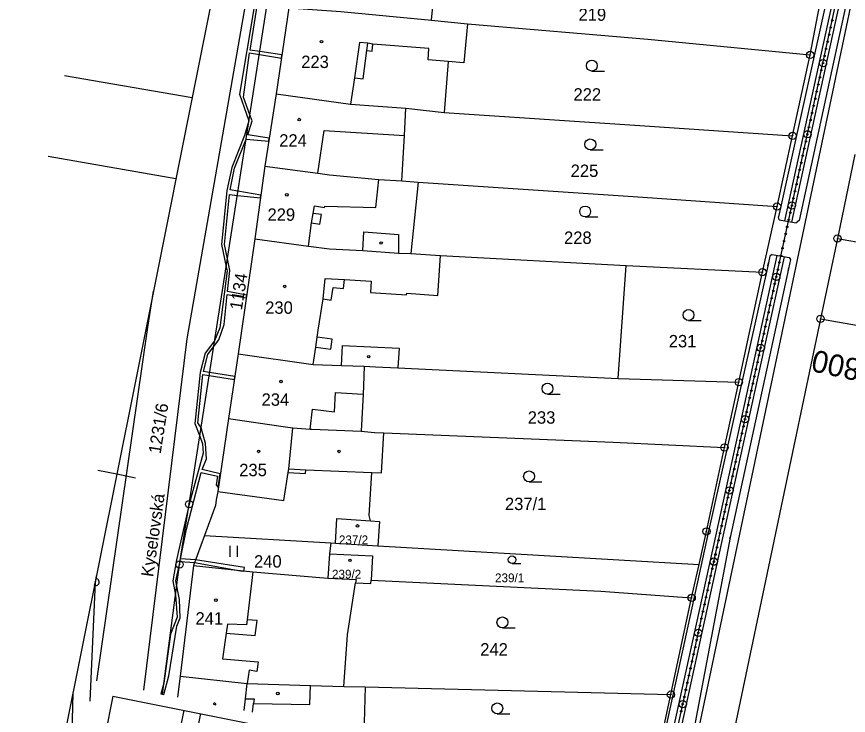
# Model space of a CAD drawing. Extents: x -548552 to -543113, y -1131925 to -1123599.
# Drawn here: x -547742 to -547627.8, y -1128838.5 to -1128742.6 of the extents above; entities that cross this region are included whole.
import ezdxf

# ---------------------------------------------------------------- set-up
doc = ezdxf.new("R2010")
doc.units = 0
for name, color, linetype in [('Hranice parcel', 7, 'Continuous'), ('HRANY', 7, 'Continuous'), ('Parcelní čísla', 7, 'Continuous'), ('Pop  PČ popisy', 7, 'Continuous'), ('Profile', 7, 'Continuous'), ('PROFILY NÁVRH', 7, 'Continuous'), ('STANIČENÍ', 7, 'Continuous'), ('Vnitřní kresba', 7, 'Continuous'), ('Vrstva 8', 7, 'Continuous'), ('Věcná břemena k části', 7, 'Continuous'), ('Značky bodu BP', 7, 'Continuous'), ('Značky budov', 7, 'Continuous'), ('Značky kultur', 7, 'Continuous')]:
    doc.layers.add(name, color=color, linetype=linetype)

msp = doc.modelspace()

# ---------------------------------------------------------------- linework, layer by layer
at = {"layer": 'Hranice parcel'}
for p, q in [((-547633.04, -1128747.88), (-547631.47, -1128739.69)), ((-547704.58, -1128741.4), (-547706.36, -1128753.23)), ((-547685.02, -1128743.12), (-547680.09, -1128743.61)), ((-547635.45, -1128758.96), (-547633.04, -1128747.88)), ((-547735.4, -1128750.68), (-547717.86, -1128753.7)), ((-547706.36, -1128753.23), (-547707.88, -1128763.12)), ((-547688.53, -1128755.18), (-547683.26, -1128755.76)), ((-547637.59, -1128768.68), (-547635.45, -1128758.96)), ((-547737.62, -1128761.78), (-547720.09, -1128764.83)), ((-547626.9, -1128761.54), (-547629.31, -1128773.05)), ((-547707.88, -1128763.12), (-547709.27, -1128773.09)), ((-547689.07, -1128765.13), (-547686.87, -1128765.32)), ((-547686.87, -1128765.32), (-547687.85, -1128775.09)), ((-547639.6, -1128777.67), (-547637.59, -1128768.68)), ((-547709.27, -1128773.09), (-547711.54, -1128788.87)), ((-547629.31, -1128773.05), (-547631.63, -1128784.07)), ((-547629.31, -1128773.05), (-547600.12, -1128778.08)), ((-547659.38, -1128792.25), (-547658.28, -1128776.77)), ((-547658.28, -1128776.77), (-547639.6, -1128777.67)), ((-547642.84, -1128792.75), (-547639.6, -1128777.67)), ((-547631.63, -1128784.07), (-547657.34, -1128906.42)), ((-547631.63, -1128784.07), (-547602.34, -1128789.17)), ((-547711.54, -1128788.87), (-547712.89, -1128797.72)), ((-547659.38, -1128792.25), (-547642.84, -1128792.75)), ((-547644.81, -1128801.71), (-547642.84, -1128792.75)), ((-547716.19, -1128813.8), (-547717.69, -1128817.92)), ((-547716.19, -1128813.8), (-547698.83, -1128814.81)), ((-547698.83, -1128814.81), (-547699.04, -1128816.28)), ((-547698.83, -1128814.81), (-547698.21, -1128814.85)), ((-547698.21, -1128814.85), (-547692.37, -1128815.19)), ((-547692.37, -1128815.19), (-547648.29, -1128817.77)), ((-547699.04, -1128816.28), (-547699.24, -1128819.63)), ((-547717.69, -1128817.92), (-547719.5, -1128833.1)), ((-547649.31, -1128822.34), (-547648.29, -1128817.77)), ((-547652.15, -1128835.61), (-547649.31, -1128822.34)), ((-547719.5, -1128833.1), (-547719.9, -1128835.94)), ((-547697.04, -1128834.48), (-547694.14, -1128834.56)), ((-547694.14, -1128834.56), (-547694.36, -1128844.22)), ((-547694.14, -1128834.56), (-547652.15, -1128835.61)), ((-547654.13, -1128844.61), (-547652.15, -1128835.61))]:
    msp.add_line(p, q, dxfattribs=at)
for points in [[(-547661.19, -1128917.7), (-547662.18, -1128906.21), (-547607.96, -1128648.53), (-547605.32, -1128634.46), (-547602.31, -1128618.85), (-547594.66, -1128568.22), (-547592.34, -1128552.17)], [(-547721.95, -1128835.53), (-547719.59, -1128817.77), (-547718.29, -1128809.48), (-547704.49, -1128721.23), (-547694.62, -1128699.9), (-547694.57, -1128699.7)], [(-547685.02, -1128743.12), (-547684.58, -1128738.45), (-547684.26, -1128735.01)], [(-547704.58, -1128741.4), (-547697.48, -1128741.93), (-547685.02, -1128743.12)], [(-547680.09, -1128743.61), (-547680.59, -1128748.96), (-547682.74, -1128748.77), (-547683.26, -1128755.76)], [(-547680.09, -1128743.61), (-547655.34, -1128745.73), (-547633.04, -1128747.88)], [(-547706.36, -1128753.23), (-547696.13, -1128754.63), (-547688.53, -1128755.18)], [(-547689.07, -1128765.13), (-547688.71, -1128758.94), (-547688.53, -1128755.18)], [(-547683.26, -1128755.76), (-547656.41, -1128757.55), (-547635.45, -1128758.96)], [(-547707.88, -1128763.12), (-547700.6, -1128764.09), (-547699.04, -1128764.34), (-547692.24, -1128764.94), (-547689.07, -1128765.13)], [(-547686.87, -1128765.32), (-547657.36, -1128767.28), (-547637.59, -1128768.68)], [(-547709.27, -1128773.09), (-547701.9, -1128774.08), (-547699.03, -1128774.45), (-547694.46, -1128774.7), (-547689.57, -1128775.05), (-547687.85, -1128775.09)], [(-547687.85, -1128775.09), (-547683.77, -1128775.4), (-547658.28, -1128776.77)], [(-547711.54, -1128788.87), (-547701.24, -1128790.31), (-547697.36, -1128790.46), (-547694.27, -1128790.57)], [(-547694.27, -1128790.57), (-547694.36, -1128793.25), (-547694.42, -1128794.38), (-547694.67, -1128799.49)], [(-547694.27, -1128790.57), (-547692.72, -1128790.65), (-547689.62, -1128790.8), (-547659.38, -1128792.25)], [(-547712.89, -1128797.72), (-547714.36, -1128807.74), (-547714.56, -1128808.88), (-547714.68, -1128809.68), (-547716.19, -1128813.8)], [(-547712.89, -1128797.72), (-547705.05, -1128798.86), (-547704.07, -1128799.01), (-547701.69, -1128799.19), (-547701.46, -1128799.21), (-547694.67, -1128799.49)], [(-547694.67, -1128799.49), (-547692.83, -1128799.64), (-547691.56, -1128799.69)], [(-547693.37, -1128811.78), (-547693.58, -1128811.04), (-547693.2, -1128805.15), (-547691.88, -1128805.2), (-547691.56, -1128799.69)], [(-547691.56, -1128799.69), (-547660.09, -1128800.98), (-547644.81, -1128801.71)], [(-547648.29, -1128817.77), (-547647.28, -1128813.22), (-547644.81, -1128801.71)], [(-547698.21, -1128814.85), (-547698.01, -1128811.44), (-547693.37, -1128811.78)], [(-547693.37, -1128811.78), (-547692.17, -1128811.88), (-547692.37, -1128815.19)], [(-547699.04, -1128816.28), (-547693.12, -1128816.58), (-547693.32, -1128819.91)], [(-547717.69, -1128817.92), (-547709.55, -1128818.79), (-547699.24, -1128819.63)], [(-547731.26, -1128820.58), (-547731.14, -1128820.17), (-547731.01, -1128819.32)], [(-547699.24, -1128819.63), (-547695.38, -1128819.81), (-547695.45, -1128820.26)], [(-547697.04, -1128834.48), (-547696.56, -1128827.4), (-547695.45, -1128820.26)], [(-547695.45, -1128820.26), (-547693.35, -1128820.39), (-547693.32, -1128819.91)], [(-547693.32, -1128819.91), (-547661.76, -1128821.44), (-547649.31, -1128822.34)], [(-547719.5, -1128833.1), (-547710.31, -1128834.1), (-547701.61, -1128834.34), (-547697.04, -1128834.48)], [(-547734.23, -1128835.38), (-547734.5, -1128844.62), (-547735.13, -1128852.83)]]:
    msp.add_lwpolyline(points, dxfattribs=at)
at = {"layer": 'HRANY'}
for p, q in [((-547637.29, -1128770.51), (-547634.95, -1128770.92)), ((-547638.26, -1128775.26), (-547635.92, -1128775.66))]:
    msp.add_line(p, q, dxfattribs=at)
at = {"layer": 'Profile'}
for p, q in [((-547702.64, -1128677.78), (-547725.75, -1128793.06)), ((-547702.64, -1128677.78), (-547725.75, -1128793.06)), ((-547702.64, -1128677.78), (-547725.75, -1128793.06)), ((-547725.75, -1128793.06), (-547748.86, -1128908.34)), ((-547725.75, -1128793.06), (-547748.86, -1128908.34)), ((-547725.75, -1128793.06), (-547748.86, -1128908.34)), ((-547725.75, -1128793.06), (-547743.85, -1128883.36)), ((-547728.22, -1128805.39), (-547730.81, -1128804.87)), ((-547725.63, -1128805.91), (-547728.22, -1128805.39))]:
    msp.add_line(p, q, dxfattribs=at)
at = {"layer": 'PROFILY NÁVRH'}
for p, q in [((-547631, -1128741.19), (-547637.38, -1128770.08)), ((-547636.53, -1128770.64), (-547629.99, -1128740.72)), ((-547635.54, -1128770.81), (-547629.01, -1128740.93)), ((-547628.2, -1128741.26), (-547634.57, -1128770.56)), ((-547637.29, -1128770.51), (-547637.38, -1128770.08)), ((-547634.57, -1128770.56), (-547634.95, -1128770.92)), ((-547645.92, -1128813.48), (-547637.56, -1128775.38)), ((-547644.94, -1128813.69), (-547636.58, -1128775.55)), ((-547638.58, -1128775.48), (-547638.83, -1128776.62)), ((-547638.26, -1128775.26), (-547638.58, -1128775.48)), ((-547635.73, -1128775.91), (-547636.02, -1128777.23)), ((-547635.92, -1128775.66), (-547635.73, -1128775.91)), ((-547638.83, -1128776.62), (-547647.04, -1128813.42)), ((-547636.02, -1128777.23), (-547644.03, -1128814.07)), ((-547647.04, -1128813.42), (-547654.58, -1128847.9)), ((-547653.49, -1128848.05), (-547645.92, -1128813.48)), ((-547652.51, -1128848.26), (-547644.94, -1128813.69)), ((-547644.03, -1128814.07), (-547650.58, -1128848.76))]:
    msp.add_line(p, q, dxfattribs=at)
at = {"layer": 'STANIČENÍ'}
for p, q in [((-547637.12, -1128775.69), (-547629.5, -1128740.83)), ((-547645.43, -1128813.59), (-547637.12, -1128775.69)), ((-547638.87, -1128776.8), (-547638.78, -1128776.4)), ((-547636.08, -1128777.54), (-547635.98, -1128777.08)), ((-547653, -1128848.16), (-547645.43, -1128813.59)), ((-547647.09, -1128813.62), (-547647, -1128813.24)), ((-547644.07, -1128814.26), (-547643.99, -1128813.9))]:
    msp.add_line(p, q, dxfattribs=at)
for centre, radius in [((-547630.22, -1128744.11), 0.1), ((-547630, -1128743.13), 0.1), ((-547630.43, -1128745.08), 0.1), ((-547630.64, -1128746.06), 0.1), ((-547630.86, -1128747.04), 0.1), ((-547631.28, -1128748.99), 0.5), ((-547631.07, -1128748.01), 0.1), ((-547631.28, -1128748.99), 0.1), ((-547631.71, -1128750.94), 0.1), ((-547631.5, -1128749.97), 0.1), ((-547631.92, -1128751.92), 0.1), ((-547632.14, -1128752.9), 0.1), ((-547632.35, -1128753.87), 0.1), ((-547632.57, -1128754.85), 0.1), ((-547632.78, -1128755.83), 0.1), ((-547633.21, -1128757.78), 0.1), ((-547632.99, -1128756.8), 0.1), ((-547633.42, -1128758.76), 0.5), ((-547633.42, -1128758.76), 0.1), ((-547633.63, -1128759.74), 0.1), ((-547633.85, -1128760.71), 0.1), ((-547634.06, -1128761.69), 0.1), ((-547634.27, -1128762.67), 0.1), ((-547634.7, -1128764.62), 0.1), ((-547634.49, -1128763.64), 0.1), ((-547634.91, -1128765.6), 0.1), ((-547635.13, -1128766.57), 0.1), ((-547635.34, -1128767.55), 0.1), ((-547635.55, -1128768.53), 0.5), ((-547635.55, -1128768.53), 0.1), ((-547635.77, -1128769.5), 0.1), ((-547636.2, -1128771.46), 0.1), ((-547635.98, -1128770.48), 0.1), ((-547636.41, -1128772.43), 0.1), ((-547636.62, -1128773.41), 0.1), ((-547636.84, -1128774.39), 0.1), ((-547637.05, -1128775.37), 0.1), ((-547637.26, -1128776.34), 0.1), ((-547637.69, -1128778.3), 0.5), ((-547637.69, -1128778.3), 0.1), ((-547637.48, -1128777.32), 0.1), ((-547637.91, -1128779.27), 0.1), ((-547638.12, -1128780.25), 0.1), ((-547638.33, -1128781.23), 0.1), ((-547638.55, -1128782.2), 0.1), ((-547638.76, -1128783.18), 0.1), ((-547639.19, -1128785.13), 0.1), ((-547638.98, -1128784.16), 0.1), ((-547639.4, -1128786.11), 0.1), ((-547639.62, -1128787.09), 0.1), ((-547639.83, -1128788.06), 0.5), ((-547639.83, -1128788.06), 0.1), ((-547640.05, -1128789.04), 0.1), ((-547640.26, -1128790.02), 0.1), ((-547640.69, -1128791.97), 0.1), ((-547640.48, -1128790.99), 0.1), ((-547640.9, -1128792.95), 0.1), ((-547641.12, -1128793.92), 0.1), ((-547641.33, -1128794.9), 0.1), ((-547641.55, -1128795.88), 0.1), ((-547641.98, -1128797.83), 0.5), ((-547641.76, -1128796.85), 0.1), ((-547642.19, -1128798.81), 0.1), ((-547641.98, -1128797.83), 0.1), ((-547642.4, -1128799.78), 0.1), ((-547642.62, -1128800.76), 0.1), ((-547642.83, -1128801.74), 0.1), ((-547643.05, -1128802.72), 0.1), ((-547643.26, -1128803.69), 0.1), ((-547643.69, -1128805.65), 0.1), ((-547643.47, -1128804.67), 0.1), ((-547643.9, -1128806.62), 0.1), ((-547644.12, -1128807.6), 0.5), ((-547644.12, -1128807.6), 0.1), ((-547644.33, -1128808.58), 0.1), ((-547644.55, -1128809.55), 0.1), ((-547644.76, -1128810.53), 0.1), ((-547645.19, -1128812.48), 0.1), ((-547644.97, -1128811.51), 0.1), ((-547645.4, -1128813.46), 0.1), ((-547645.62, -1128814.44), 0.1), ((-547645.83, -1128815.41), 0.1), ((-547646.26, -1128817.37), 0.5), ((-547646.04, -1128816.39), 0.1), ((-547646.26, -1128817.37), 0.1), ((-547646.69, -1128819.32), 0.1), ((-547646.47, -1128818.34), 0.1), ((-547646.9, -1128820.3), 0.1), ((-547647.11, -1128821.27), 0.1), ((-547647.33, -1128822.25), 0.1), ((-547647.54, -1128823.23), 0.1), ((-547647.97, -1128825.18), 0.1), ((-547647.75, -1128824.21), 0.1), ((-547648.18, -1128826.16), 0.1), ((-547648.4, -1128827.14), 0.5), ((-547648.4, -1128827.14), 0.1), ((-547648.61, -1128828.11), 0.1), ((-547648.82, -1128829.09), 0.1), ((-547649.04, -1128830.07), 0.1), ((-547649.47, -1128832.02), 0.1), ((-547649.25, -1128831.04), 0.1), ((-547649.68, -1128833), 0.1), ((-547649.89, -1128833.97), 0.1), ((-547650.11, -1128834.95), 0.1), ((-547650.54, -1128836.9), 0.5), ((-547650.32, -1128835.93), 0.1), ((-547650.54, -1128836.9), 0.1), ((-547650.75, -1128837.88), 0.1)]:
    msp.add_circle(centre, radius, dxfattribs=at)
at = {"layer": 'Vnitřní kresba'}
for p, q in [((-547706.72, -1128718.76), (-547718.58, -1128786.8)), ((-547694.89, -1128746.15), (-547695.6, -1128751.02)), ((-547693.77, -1128746.25), (-547694.89, -1128746.15)), ((-547693.91, -1128747.26), (-547693.77, -1128746.25)), ((-547693.06, -1128746.39), (-547693.77, -1128746.25)), ((-547694.41, -1128751.16), (-547693.91, -1128747.26)), ((-547693.91, -1128747.26), (-547693.18, -1128747.36)), ((-547693.18, -1128747.36), (-547693.06, -1128746.39)), ((-547685.38, -1128747.01), (-547693.06, -1128746.39)), ((-547685.47, -1128748.54), (-547685.38, -1128747.01)), ((-547682.74, -1128748.77), (-547685.47, -1128748.54)), ((-547695.6, -1128751.02), (-547696.13, -1128754.63)), ((-547695.6, -1128751.02), (-547694.41, -1128751.16)), ((-547700.6, -1128764.09), (-547699.76, -1128758.26)), ((-547699.76, -1128758.26), (-547688.71, -1128758.94)), ((-547692.67, -1128768.8), (-547692.24, -1128764.94)), ((-547701.25, -1128769.63), (-547701.09, -1128768.59)), ((-547701.09, -1128768.59), (-547699.7, -1128768.8)), ((-547699.7, -1128768.8), (-547699.67, -1128768.6)), ((-547699.67, -1128768.6), (-547692.67, -1128768.8)), ((-547701.47, -1128770.92), (-547701.25, -1128769.63)), ((-547700.13, -1128769.78), (-547701.25, -1128769.63)), ((-547700.35, -1128771.07), (-547700.13, -1128769.78)), ((-547701.9, -1128774.08), (-547701.47, -1128770.92)), ((-547701.47, -1128770.92), (-547700.35, -1128771.07)), ((-547694.46, -1128774.7), (-547694.3, -1128772.15)), ((-547694.3, -1128772.15), (-547689.56, -1128772.5)), ((-547689.56, -1128772.5), (-547689.57, -1128775.05)), ((-547684.14, -1128780.85), (-547683.77, -1128775.4)), ((-547699.91, -1128781.32), (-547699.6, -1128778.53)), ((-547699.6, -1128778.53), (-547696.97, -1128778.67)), ((-547697.12, -1128779.89), (-547696.97, -1128778.67)), ((-547696.97, -1128778.67), (-547693.29, -1128778.92)), ((-547693.29, -1128778.92), (-547693.4, -1128780.46)), ((-547723.95, -1128785.22), (-547723.18, -1128780.27)), ((-547698.81, -1128781.51), (-547698.51, -1128779.76)), ((-547698.51, -1128779.76), (-547697.12, -1128779.89)), ((-547693.4, -1128780.46), (-547688.43, -1128780.76)), ((-547688.43, -1128780.76), (-547688.41, -1128780.53)), ((-547688.41, -1128780.53), (-547684.14, -1128780.85)), ((-547700.59, -1128785.62), (-547699.91, -1128781.32)), ((-547699.91, -1128781.32), (-547698.81, -1128781.51)), ((-547730.95, -1128833.73), (-547723.95, -1128785.22)), ((-547700.72, -1128786.58), (-547700.59, -1128785.62)), ((-547718.58, -1128786.8), (-547724.54, -1128835.01)), ((-547700.91, -1128787.95), (-547700.72, -1128786.58)), ((-547698.64, -1128786.87), (-547700.72, -1128786.58)), ((-547698.83, -1128788.24), (-547698.64, -1128786.87)), ((-547701.24, -1128790.31), (-547700.91, -1128787.95)), ((-547700.91, -1128787.95), (-547698.83, -1128788.24)), ((-547697.36, -1128790.46), (-547697.22, -1128787.72)), ((-547697.22, -1128787.72), (-547689.48, -1128788.1)), ((-547689.48, -1128788.1), (-547689.62, -1128790.8)), ((-547704.62, -1128804.66), (-547704.07, -1128799.01)), ((-547705.28, -1128808.98), (-547704.7, -1128805.15)), ((-547704.7, -1128805.15), (-547704.62, -1128804.66)), ((-547704.7, -1128805.15), (-547702.31, -1128805.29)), ((-547704.62, -1128804.66), (-547702.28, -1128804.8)), ((-547702.31, -1128805.29), (-547702.28, -1128804.8)), ((-547702.28, -1128804.8), (-547693.2, -1128805.15)), ((-547714.36, -1128807.74), (-547705.28, -1128808.98)), ((-547709.55, -1128818.79), (-547710.33, -1128825.35)), ((-547731.86, -1128836.52), (-547731.14, -1128820.17)), ((-547713.04, -1128825.95), (-547713.22, -1128827.2)), ((-547710.42, -1128826.05), (-547713.04, -1128825.95)), ((-547710.33, -1128825.35), (-547710.42, -1128826.05)), ((-547708.95, -1128825.46), (-547710.33, -1128825.35)), ((-547709.23, -1128827.52), (-547708.95, -1128825.46)), ((-547713.22, -1128827.2), (-547713.72, -1128830.7)), ((-547713.22, -1128827.2), (-547709.23, -1128827.52)), ((-547713.72, -1128830.7), (-547708.82, -1128831.1)), ((-547708.82, -1128831.1), (-547709, -1128832.44)), ((-547710.06, -1128832.26), (-547710.31, -1128834.1)), ((-547709, -1128832.44), (-547710.06, -1128832.26)), ((-547710.54, -1128836.18), (-547710.31, -1128834.1)), ((-547701.72, -1128836.96), (-547701.61, -1128834.34)), ((-547710.71, -1128837.78), (-547710.54, -1128836.18)), ((-547710.54, -1128836.18), (-547709.38, -1128836.19)), ((-547709.38, -1128836.19), (-547709.45, -1128836.81)), ((-547709.58, -1128838.01), (-547709.45, -1128836.81)), ((-547709.45, -1128836.81), (-547701.72, -1128836.96))]:
    msp.add_line(p, q, dxfattribs=at)
msp.add_lwpolyline([(-547701.69, -1128799.19), (-547701.37, -1128796.47), (-547698.32, -1128796.83), (-547698.21, -1128794.18), (-547694.42, -1128794.38)], dxfattribs=at)
at = {"layer": 'Vrstva 8'}
for p, q in [((-547728.77, -1128835.8), (-547741.95, -1128901.53)), ((-547728.77, -1128835.8), (-547702.68, -1128841.02)), ((-547719.03, -1128837.75), (-547732.21, -1128903.48)), ((-547716.74, -1128838.21), (-547729.92, -1128903.94))]:
    msp.add_line(p, q, dxfattribs=at)
at = {"layer": 'Věcná břemena k části'}
msp.add_line((-547722.16, -1128835.49), (-547721.75, -1128835.57), dxfattribs=at)
for points in [[(-547719.99, -1128826.2), (-547719.53, -1128825.06), (-547719.62, -1128822.56), (-547719.98, -1128820.72), (-547720.12, -1128820.02), (-547719.53, -1128817.37), (-547717.54, -1128817.51), (-547711.25, -1128818.61), (-547710.78, -1128818.66), (-547710.7, -1128818.19), (-547717.39, -1128817.11), (-547719.46, -1128816.97), (-547718.64, -1128812.93), (-547716.64, -1128805.13), (-547714.4, -1128805.65), (-547714.56, -1128806.82), (-547714.28, -1128807.18), (-547714.01, -1128805.33), (-547716.51, -1128804.75), (-547715.92, -1128803.27), (-547716.04, -1128801.17), (-547716.65, -1128799.01), (-547717.09, -1128798.34), (-547716.39, -1128791.69), (-547715.53, -1128791.83), (-547712.08, -1128792.38), (-547712.01, -1128791.98), (-547715.47, -1128791.43), (-547716.32, -1128791.3), (-547715.71, -1128788.98), (-547714.92, -1128787.93), (-547714.2, -1128786.97), (-547713.46, -1128784.84), (-547713.07, -1128780.71), (-547710.44, -1128781.21), (-547710.38, -1128780.81), (-547713.03, -1128780.31), (-547712.68, -1128777.45), (-547713.03, -1128775.82), (-547713.45, -1128773.87), (-547712.75, -1128767.03), (-547711.67, -1128767.15), (-547708.49, -1128767.49), (-547708.43, -1128767.09), (-547711.58, -1128766.56), (-547712.66, -1128766.37), (-547712.05, -1128763.42), (-547710.46, -1128759.44), (-547707.36, -1128759.72), (-547707.3, -1128759.31), (-547710.25, -1128758.85), (-547709.64, -1128756.91), (-547709.94, -1128756.08), (-547710.81, -1128753.65), (-547710.02, -1128747.6), (-547708.65, -1128747.82), (-547705.62, -1128748.3), (-547705.55, -1128747.86), (-547708.58, -1128747.41), (-547709.91, -1128747.21), (-547708.29, -1128737.09)], [(-547709.41, -1128741.53), (-547711.38, -1128753.25), (-547710.07, -1128756.9), (-547710.7, -1128758.94), (-547712.43, -1128763.3), (-547713.1, -1128766.49), (-547713.85, -1128773.89), (-547713.2, -1128776.93), (-547713.08, -1128777.47), (-547714.05, -1128785.3), (-547714.79, -1128787.09), (-547716.07, -1128788.8), (-547716.77, -1128791.43), (-547717.5, -1128798.41), (-547716.83, -1128800.17), (-547716.44, -1128801.23), (-547716.36, -1128802.47), (-547718.29, -1128809.48), (-547720.01, -1128817.11), (-547720.52, -1128820.02), (-547720.15, -1128821.95), (-547719.93, -1128824.98), (-547720.85, -1128827.3), (-547721.75, -1128834.03), (-547722.16, -1128835.49)], [(-547721.75, -1128835.57), (-547721.05, -1128833.04), (-547719.99, -1128826.2)]]:
    msp.add_lwpolyline(points, dxfattribs=at)
at = {"layer": 'Značky bodu BP'}
msp.add_line((-547731.08, -1128819.67), (-547731.28, -1128820.65), dxfattribs=at)
for centre, radius in [((-547633.04, -1128747.88), 0.5), ((-547633.04, -1128747.88), 0.0303), ((-547635.45, -1128758.96), 0.5), ((-547635.45, -1128758.96), 0.0303), ((-547637.59, -1128768.68), 0.5), ((-547637.59, -1128768.68), 0.0303), ((-547629.31, -1128773.05), 0.5), ((-547629.31, -1128773.05), 0.0303), ((-547639.6, -1128777.67), 0.5), ((-547639.6, -1128777.67), 0.0303), ((-547631.63, -1128784.07), 0.5), ((-547631.63, -1128784.07), 0.0303), ((-547642.84, -1128792.75), 0.5), ((-547642.84, -1128792.75), 0.0303), ((-547644.81, -1128801.71), 0.5), ((-547644.81, -1128801.71), 0.0303), ((-547718.29, -1128809.48), 0.5), ((-547718.29, -1128809.48), 0.0303), ((-547647.28, -1128813.22), 0.5), ((-547647.28, -1128813.22), 0.0303), ((-547719.59, -1128817.77), 0.5), ((-547719.59, -1128817.77), 0.0303), ((-547731.14, -1128820.17), 0.0303), ((-547649.31, -1128822.34), 0.5), ((-547649.31, -1128822.34), 0.0303), ((-547652.15, -1128835.61), 0.5), ((-547652.15, -1128835.61), 0.0303)]:
    msp.add_circle(centre, radius, dxfattribs=at)
msp.add_arc((-547731.14, -1128820.17), 0.5, 253.9909, 83.3399, dxfattribs=at)
at = {"layer": 'Značky budov'}
msp.add_line((-547714.96, -1128836.93), (-547714.62, -1128837), dxfattribs=at)
for centre in [(-547700.12, -1128746.05), (-547703.17, -1128756.74), (-547704.87, -1128767.06), (-547691.94, -1128773.67), (-547705.17, -1128779.62), (-547693.64, -1128789.25), (-547705.67, -1128792.67), (-547708.75, -1128802.25), (-547697.71, -1128802.25), (-547695.18, -1128812.47), (-547696.21, -1128817.19), (-547714.61, -1128822.65), (-547706.12, -1128835.46)]:
    msp.add_circle(centre, 0.175, dxfattribs=at)
msp.add_arc((-547714.79, -1128836.95), 0.175, 341.7014, 175.6294, dxfattribs=at)
at = {"layer": 'Značky kultur'}
for p, q in [((-547663.01, -1128750.09), (-547661.26, -1128750.09)), ((-547663.22, -1128760.9), (-547661.47, -1128760.9)), ((-547663.93, -1128770.1), (-547662.18, -1128770.1)), ((-547649.74, -1128784.29), (-547647.99, -1128784.29)), ((-547669.1, -1128794.4), (-547667.35, -1128794.4)), ((-547671.63, -1128806.43), (-547669.88, -1128806.43)), ((-547712.67, -1128816.69), (-547712.67, -1128815.19)), ((-547711.67, -1128816.69), (-547711.67, -1128815.19)), ((-547673.96, -1128817.64), (-547672.74, -1128817.64)), ((-547675.29, -1128826.45), (-547673.54, -1128826.45)), ((-547676, -1128838.25), (-547674.25, -1128838.25))]:
    msp.add_line(p, q, dxfattribs=at)
for centre, radius in [((-547663.01, -1128749.34), 0.75), ((-547663.22, -1128760.15), 0.75), ((-547663.93, -1128769.35), 0.75), ((-547649.74, -1128783.54), 0.75), ((-547669.1, -1128793.65), 0.75), ((-547671.63, -1128805.68), 0.75), ((-547673.96, -1128817.11), 0.525), ((-547675.29, -1128825.7), 0.75), ((-547676, -1128837.5), 0.75)]:
    msp.add_circle(centre, radius, dxfattribs=at)

# ---------------------------------------------------------------- texts
at = {"layer": 'Parcelní čísla'}
for s, height, p in [('219', 1.7, (-547664.84, -1128743.19)), ('223', 1.7, (-547702.9, -1128749.67)), ('222', 1.7, (-547665.53, -1128754.14)), ('224', 1.7, (-547705.92, -1128760.45)), ('225', 1.7, (-547665.92, -1128764.61)), ('229', 1.7, (-547707.53, -1128770.62)), ('228', 1.7, (-547666.83, -1128773.79)), ('230', 1.7, (-547707.85, -1128783.38)), ('231', 1.7, (-547652.45, -1128787.98)), ('234', 1.7, (-547708.34, -1128795.99)), ('233', 1.7, (-547671.81, -1128798.45)), ('235', 1.7, (-547711.41, -1128805.65)), ('237/1', 1.7, (-547674.94, -1128810.3)), ('237/2', 1.2, (-547697.73, -1128814.98)), ('240', 1.7, (-547709.38, -1128818.19)), ('239/2', 1.2, (-547698.68, -1128819.69)), ('239/1', 1.2, (-547676.3, -1128820.19)), ('241', 1.7, (-547717.41, -1128826)), ('242', 1.7, (-547678.33, -1128830.25))]:
    msp.add_text(s, height=height, dxfattribs=at).set_placement(p)
for s, p in [('1134', (-547711.05, -1128782.95)), ('1231/6', (-547722.2, -1128802.65))]:
    msp.add_text(s, height=1.7, rotation=81, dxfattribs=at).set_placement(p)
at = {"layer": 'Pop  PČ popisy'}
msp.add_text('Kyselovská', height=1.7, rotation=82, dxfattribs=at).set_placement((-547723.22, -1128819.54))
at = {"layer": 'STANIČENÍ'}
msp.add_text('2,800', height=3, rotation=167.633, dxfattribs=at).set_placement((-547622.62, -1128790.42))

doc.saveas('drawing.dxf')
